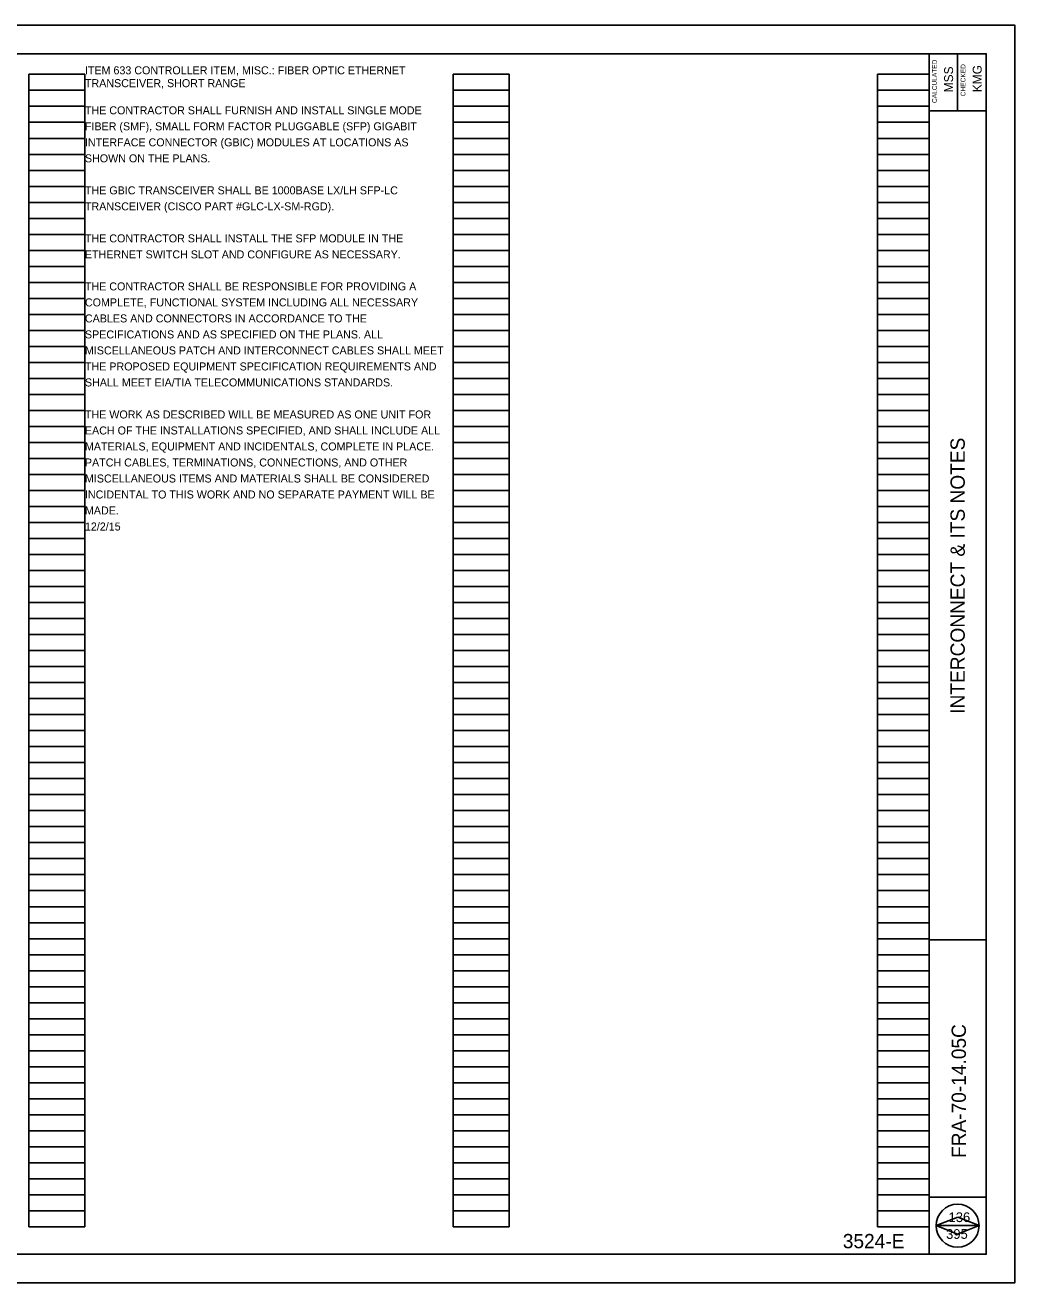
# Model space of a CAD drawing. Extents: x -41.3 to 53.7, y -40.1 to 14.5.
# Drawn here: x 16.19 to 33.49, y -7.51 to 14.49 of the extents above; entities that cross this region are included whole.
import ezdxf

# ---------------------------------------------------------------- set-up
doc = ezdxf.new("R2010")
doc.units = 0
for name, color, linetype in [('Level 63', 7, 'Continuous'), ('PF_P_Text', 7, 'Continuous'), ('SC_Scratch1', 7, 'Continuous'), ('SH_Cut_Line', 7, 'Continuous'), ('SH_Data', 7, 'Continuous'), ('SH_Text', 7, 'Continuous')]:
    doc.layers.add(name, color=color, linetype=linetype)

msp = doc.modelspace()

# ---------------------------------------------------------------- linework, layer by layer
at = {"layer": 'Level 63'}
msp.add_line((32.119, -6.508), (32.869, -6.508), dxfattribs=at)
msp.add_line((32.119, -6.508), (32.869, -6.508), dxfattribs=at)
msp.add_circle((32.494, -6.508), 0.375, dxfattribs=at)
at = {"layer": 'PF_P_Text'}
for p, q in [((31.994, -7.008), (31.994, 13.992)), ((32.494, 13.992), (32.494, 12.992)), ((31.994, 12.992), (32.994, 12.992)), ((31.994, -1.508), (32.994, -1.508)), ((31.994, -6.008), (32.994, -6.008))]:
    msp.add_line(p, q, dxfattribs=at)
msp.add_lwpolyline([(1.494, 13.992), (32.994, 13.992), (32.994, -7.008), (1.494, -7.008)], close=True, dxfattribs=at)
at = {"layer": 'SC_Scratch1'}
for p, q in [((16.254, -6.528), (16.254, 13.632)), ((16.254, 13.632), (17.234, 13.632)), ((17.234, -6.528), (17.234, 13.632)), ((23.674, -6.528), (23.674, 13.632)), ((23.674, 13.632), (24.654, 13.632)), ((24.654, -6.528), (24.654, 13.632)), ((31.094, -6.528), (31.094, 13.632)), ((31.094, 13.632), (31.994, 13.632)), ((31.994, -6.528), (31.994, 13.632)), ((16.254, 13.352), (17.234, 13.352)), ((23.674, 13.352), (24.654, 13.352)), ((31.094, 13.352), (31.994, 13.352)), ((16.254, 13.072), (17.234, 13.072)), ((23.674, 13.072), (24.654, 13.072)), ((31.094, 13.072), (31.994, 13.072)), ((16.254, 12.792), (17.234, 12.792)), ((23.674, 12.792), (24.654, 12.792)), ((31.094, 12.792), (31.994, 12.792)), ((16.254, 12.512), (17.234, 12.512)), ((23.674, 12.512), (24.654, 12.512)), ((31.094, 12.512), (31.994, 12.512)), ((16.254, 12.232), (17.234, 12.232)), ((23.674, 12.232), (24.654, 12.232)), ((31.094, 12.232), (31.994, 12.232)), ((16.254, 11.952), (17.234, 11.952)), ((23.674, 11.952), (24.654, 11.952)), ((31.094, 11.952), (31.994, 11.952)), ((16.254, 11.672), (17.234, 11.672)), ((23.674, 11.672), (24.654, 11.672)), ((31.094, 11.672), (31.994, 11.672)), ((16.254, 11.392), (17.234, 11.392)), ((23.674, 11.392), (24.654, 11.392)), ((31.094, 11.392), (31.994, 11.392)), ((16.254, 11.112), (17.234, 11.112)), ((23.674, 11.112), (24.654, 11.112)), ((31.094, 11.112), (31.994, 11.112)), ((16.254, 10.832), (17.234, 10.832)), ((23.674, 10.832), (24.654, 10.832)), ((31.094, 10.832), (31.994, 10.832)), ((16.254, 10.552), (17.234, 10.552)), ((23.674, 10.552), (24.654, 10.552)), ((31.094, 10.552), (31.994, 10.552)), ((16.254, 10.272), (17.234, 10.272)), ((23.674, 10.272), (24.654, 10.272)), ((31.094, 10.272), (31.994, 10.272)), ((16.254, 9.992), (17.234, 9.992)), ((23.674, 9.992), (24.654, 9.992)), ((31.094, 9.992), (31.994, 9.992)), ((16.254, 9.712), (17.234, 9.712)), ((23.674, 9.712), (24.654, 9.712)), ((31.094, 9.712), (31.994, 9.712)), ((16.254, 9.432), (17.234, 9.432)), ((23.674, 9.432), (24.654, 9.432)), ((31.094, 9.432), (31.994, 9.432)), ((16.254, 9.152), (17.234, 9.152)), ((23.674, 9.152), (24.654, 9.152)), ((31.094, 9.152), (31.994, 9.152)), ((16.254, 8.872), (17.234, 8.872)), ((23.674, 8.872), (24.654, 8.872)), ((31.094, 8.872), (31.994, 8.872)), ((16.254, 8.592), (17.234, 8.592)), ((23.674, 8.592), (24.654, 8.592)), ((31.094, 8.592), (31.994, 8.592)), ((16.254, 8.312), (17.234, 8.312)), ((23.674, 8.312), (24.654, 8.312)), ((31.094, 8.312), (31.994, 8.312)), ((16.254, 8.032), (17.234, 8.032)), ((23.674, 8.032), (24.654, 8.032)), ((31.094, 8.032), (31.994, 8.032)), ((16.254, 7.752), (17.234, 7.752)), ((23.674, 7.752), (24.654, 7.752)), ((31.094, 7.752), (31.994, 7.752)), ((16.254, 7.472), (17.234, 7.472)), ((23.674, 7.472), (24.654, 7.472)), ((31.094, 7.472), (31.994, 7.472)), ((16.254, 7.192), (17.234, 7.192)), ((23.674, 7.192), (24.654, 7.192)), ((31.094, 7.192), (31.994, 7.192)), ((16.254, 6.912), (17.234, 6.912)), ((23.674, 6.912), (24.654, 6.912)), ((31.094, 6.912), (31.994, 6.912)), ((16.254, 6.632), (17.234, 6.632)), ((23.674, 6.632), (24.654, 6.632)), ((31.094, 6.632), (31.994, 6.632)), ((16.254, 6.352), (17.234, 6.352)), ((23.674, 6.352), (24.654, 6.352)), ((31.094, 6.352), (31.994, 6.352)), ((16.254, 6.072), (17.234, 6.072)), ((23.674, 6.072), (24.654, 6.072)), ((31.094, 6.072), (31.994, 6.072)), ((16.254, 5.792), (17.234, 5.792)), ((23.674, 5.792), (24.654, 5.792)), ((31.094, 5.792), (31.994, 5.792)), ((16.254, 5.512), (17.234, 5.512)), ((23.674, 5.512), (24.654, 5.512)), ((31.094, 5.512), (31.994, 5.512)), ((16.254, 5.232), (17.234, 5.232)), ((23.674, 5.232), (24.654, 5.232)), ((31.094, 5.232), (31.994, 5.232)), ((16.254, 4.952), (17.234, 4.952)), ((23.674, 4.952), (24.654, 4.952)), ((31.094, 4.952), (31.994, 4.952)), ((16.254, 4.672), (17.234, 4.672)), ((23.674, 4.672), (24.654, 4.672)), ((31.094, 4.672), (31.994, 4.672)), ((16.254, 4.392), (17.234, 4.392)), ((23.674, 4.392), (24.654, 4.392)), ((31.094, 4.392), (31.994, 4.392)), ((16.254, 4.112), (17.234, 4.112)), ((23.674, 4.112), (24.654, 4.112)), ((31.094, 4.112), (31.994, 4.112)), ((16.254, 3.832), (17.234, 3.832)), ((23.674, 3.832), (24.654, 3.832)), ((31.094, 3.832), (31.994, 3.832)), ((16.254, 3.552), (17.234, 3.552)), ((23.674, 3.552), (24.654, 3.552)), ((31.094, 3.552), (31.994, 3.552)), ((16.254, 3.272), (17.234, 3.272)), ((23.674, 3.272), (24.654, 3.272)), ((31.094, 3.272), (31.994, 3.272)), ((16.254, 2.992), (17.234, 2.992)), ((23.674, 2.992), (24.654, 2.992)), ((31.094, 2.992), (31.994, 2.992)), ((16.254, 2.712), (17.234, 2.712)), ((23.674, 2.712), (24.654, 2.712)), ((31.094, 2.712), (31.994, 2.712)), ((16.254, 2.432), (17.234, 2.432)), ((23.674, 2.432), (24.654, 2.432)), ((31.094, 2.432), (31.994, 2.432)), ((16.254, 2.152), (17.234, 2.152)), ((23.674, 2.152), (24.654, 2.152)), ((31.094, 2.152), (31.994, 2.152)), ((16.254, 1.872), (17.234, 1.872)), ((23.674, 1.872), (24.654, 1.872)), ((31.094, 1.872), (31.994, 1.872)), ((16.254, 1.592), (17.234, 1.592)), ((23.674, 1.592), (24.654, 1.592)), ((31.094, 1.592), (31.994, 1.592)), ((16.254, 1.312), (17.234, 1.312)), ((23.674, 1.312), (24.654, 1.312)), ((31.094, 1.312), (31.994, 1.312)), ((16.254, 1.032), (17.234, 1.032)), ((23.674, 1.032), (24.654, 1.032)), ((31.094, 1.032), (31.994, 1.032)), ((16.254, 0.752), (17.234, 0.752)), ((23.674, 0.752), (24.654, 0.752)), ((31.094, 0.752), (31.994, 0.752)), ((16.254, 0.472), (17.234, 0.472)), ((23.674, 0.472), (24.654, 0.472)), ((31.094, 0.472), (31.994, 0.472)), ((16.254, 0.192), (17.234, 0.192)), ((23.674, 0.192), (24.654, 0.192)), ((31.094, 0.192), (31.994, 0.192)), ((16.254, -0.088), (17.234, -0.088)), ((23.674, -0.088), (24.654, -0.088)), ((31.094, -0.088), (31.994, -0.088)), ((16.254, -0.368), (17.234, -0.368)), ((23.674, -0.368), (24.654, -0.368)), ((31.094, -0.368), (31.994, -0.368)), ((16.254, -0.648), (17.234, -0.648)), ((23.674, -0.648), (24.654, -0.648)), ((31.094, -0.648), (31.994, -0.648)), ((16.254, -0.928), (17.234, -0.928)), ((23.674, -0.928), (24.654, -0.928)), ((31.094, -0.928), (31.994, -0.928)), ((16.254, -1.208), (17.234, -1.208)), ((23.674, -1.208), (24.654, -1.208)), ((31.094, -1.208), (31.994, -1.208)), ((16.254, -1.488), (17.234, -1.488)), ((23.674, -1.488), (24.654, -1.488)), ((31.094, -1.488), (31.994, -1.488)), ((16.254, -1.768), (17.234, -1.768)), ((23.674, -1.768), (24.654, -1.768)), ((31.094, -1.768), (31.994, -1.768)), ((16.254, -2.048), (17.234, -2.048)), ((23.674, -2.048), (24.654, -2.048)), ((31.094, -2.048), (31.994, -2.048)), ((16.254, -2.328), (17.234, -2.328)), ((23.674, -2.328), (24.654, -2.328)), ((31.094, -2.328), (31.994, -2.328)), ((16.254, -2.608), (17.234, -2.608)), ((23.674, -2.608), (24.654, -2.608)), ((31.094, -2.608), (31.994, -2.608)), ((16.254, -2.888), (17.234, -2.888)), ((23.674, -2.888), (24.654, -2.888)), ((31.094, -2.888), (31.994, -2.888)), ((16.254, -3.168), (17.234, -3.168)), ((23.674, -3.168), (24.654, -3.168)), ((31.094, -3.168), (31.994, -3.168)), ((16.254, -3.448), (17.234, -3.448)), ((23.674, -3.448), (24.654, -3.448)), ((31.094, -3.448), (31.994, -3.448)), ((16.254, -3.728), (17.234, -3.728)), ((23.674, -3.728), (24.654, -3.728)), ((31.094, -3.728), (31.994, -3.728)), ((16.254, -4.008), (17.234, -4.008)), ((23.674, -4.008), (24.654, -4.008)), ((31.094, -4.008), (31.994, -4.008)), ((16.254, -4.288), (17.234, -4.288)), ((23.674, -4.288), (24.654, -4.288)), ((31.094, -4.288), (31.994, -4.288)), ((16.254, -4.568), (17.234, -4.568)), ((23.674, -4.568), (24.654, -4.568)), ((31.094, -4.568), (31.994, -4.568)), ((16.254, -4.848), (17.234, -4.848)), ((23.674, -4.848), (24.654, -4.848)), ((31.094, -4.848), (31.994, -4.848)), ((16.254, -5.128), (17.234, -5.128)), ((23.674, -5.128), (24.654, -5.128)), ((31.094, -5.128), (31.994, -5.128)), ((16.254, -5.408), (17.234, -5.408)), ((23.674, -5.408), (24.654, -5.408)), ((31.094, -5.408), (31.994, -5.408)), ((16.254, -5.688), (17.234, -5.688)), ((23.674, -5.688), (24.654, -5.688)), ((31.094, -5.688), (31.994, -5.688)), ((16.254, -5.968), (17.234, -5.968)), ((23.674, -5.968), (24.654, -5.968)), ((31.094, -5.968), (31.994, -5.968)), ((16.254, -6.248), (17.234, -6.248)), ((23.674, -6.248), (24.654, -6.248)), ((31.094, -6.248), (31.994, -6.248)), ((32.119, -6.508), (32.495, -6.36)), ((32.495, -6.36), (32.869, -6.508)), ((16.254, -6.528), (17.234, -6.528)), ((23.674, -6.528), (24.654, -6.528)), ((31.094, -6.528), (31.994, -6.528)), ((32.49, -6.654), (32.119, -6.508)), ((32.869, -6.508), (32.49, -6.654))]:
    msp.add_line(p, q, dxfattribs=at)
at = {"layer": 'SH_Cut_Line'}
msp.add_lwpolyline([(-0.506, -7.508), (33.494, -7.508), (33.494, 14.492), (-0.506, 14.492)], close=True, dxfattribs=at)

# ---------------------------------------------------------------- texts
at = {"layer": 'Level 63'}
for s, p in [('CALCULATED', (32.13, 13.129)), ('CHECKED', (32.63, 13.248))]:
    msp.add_text(s, height=0.0833, rotation=90, dxfattribs=at).set_placement(p)
at = {"layer": 'SH_Data'}
for s, p in [('ITEM 633 CONTROLLER ITEM, MISC.: FIBER OPTIC ETHERNET ', (17.234, 13.632)), ('TRANSCEIVER, SHORT RANGE', (17.234, 13.407))]:
    msp.add_text(s, height=0.14, dxfattribs=at).set_placement(p)
at = {"layer": 'SH_Text'}
for s, height, rotation, p in [('MSS', 0.156, 90, (32.414, 13.317)), ('KMG', 0.156, 90, (32.914, 13.319)), ('INTERCONNECT & ITS NOTES', 0.25, 90, (32.619, 2.447)), ('FRA-70-14.05C', 0.25, 90, (32.639, -5.324)), ('3524-E', 0.25, 359.9999, (30.486, -6.903))]:
    msp.add_text(s, height=height, rotation=rotation, dxfattribs=at).set_placement(p)
for s, height, p in [('THE CONTRACTOR SHALL FURNISH AND INSTALL SINGLE MODE ', 0.14, (17.234, 12.932)), ('FIBER (SMF), SMALL FORM FACTOR PLUGGABLE (SFP) GIGABIT ', 0.14, (17.234, 12.652)), ('INTERFACE CONNECTOR (GBIC) MODULES AT LOCATIONS AS ', 0.14, (17.234, 12.372)), ('SHOWN ON THE PLANS. ', 0.14, (17.234, 12.092)), ('THE GBIC TRANSCEIVER SHALL BE 1000BASE LX/LH SFP-LC ', 0.14, (17.234, 11.532)), ('TRANSCEIVER (CISCO PART #GLC-LX-SM-RGD).  ', 0.14, (17.234, 11.252)), ('THE CONTRACTOR SHALL INSTALL THE SFP MODULE IN THE ', 0.14, (17.234, 10.692)), ('ETHERNET SWITCH SLOT AND CONFIGURE AS NECESSARY.', 0.14, (17.234, 10.412)), ('THE CONTRACTOR SHALL BE RESPONSIBLE FOR PROVIDING A ', 0.14, (17.234, 9.852)), ('COMPLETE, FUNCTIONAL SYSTEM INCLUDING ALL NECESSARY ', 0.14, (17.234, 9.572)), ('CABLES AND CONNECTORS IN ACCORDANCE TO THE ', 0.14, (17.234, 9.292)), ('SPECIFICATIONS AND AS SPECIFIED ON THE PLANS. ALL ', 0.14, (17.234, 9.012)), ('MISCELLANEOUS PATCH AND INTERCONNECT CABLES SHALL MEET ', 0.14, (17.234, 8.732)), ('THE PROPOSED EQUIPMENT SPECIFICATION REQUIREMENTS AND ', 0.14, (17.234, 8.452)), ('SHALL MEET EIA/TIA TELECOMMUNICATIONS STANDARDS.', 0.14, (17.234, 8.172)), ('THE WORK AS DESCRIBED WILL BE MEASURED AS ONE UNIT FOR ', 0.14, (17.234, 7.612)), ('EACH OF THE INSTALLATIONS SPECIFIED, AND SHALL INCLUDE ALL ', 0.14, (17.234, 7.332)), ('MATERIALS, EQUIPMENT AND INCIDENTALS, COMPLETE IN PLACE. ', 0.14, (17.234, 7.052)), ('PATCH CABLES, TERMINATIONS, CONNECTIONS, AND OTHER ', 0.14, (17.234, 6.772)), ('MISCELLANEOUS ITEMS AND MATERIALS SHALL BE CONSIDERED ', 0.14, (17.234, 6.492)), ('INCIDENTAL TO THIS WORK AND NO SEPARATE PAYMENT WILL BE ', 0.14, (17.234, 6.212)), ('MADE.', 0.14, (17.234, 5.932)), ('12/2/15', 0.14, (17.234, 5.652)), ('136', 0.17, (32.335, -6.445)), ('395', 0.17, (32.292, -6.739))]:
    msp.add_text(s, height=height, dxfattribs=at).set_placement(p)

doc.saveas('drawing.dxf')
